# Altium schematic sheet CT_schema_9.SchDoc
size 254 x 194 mm
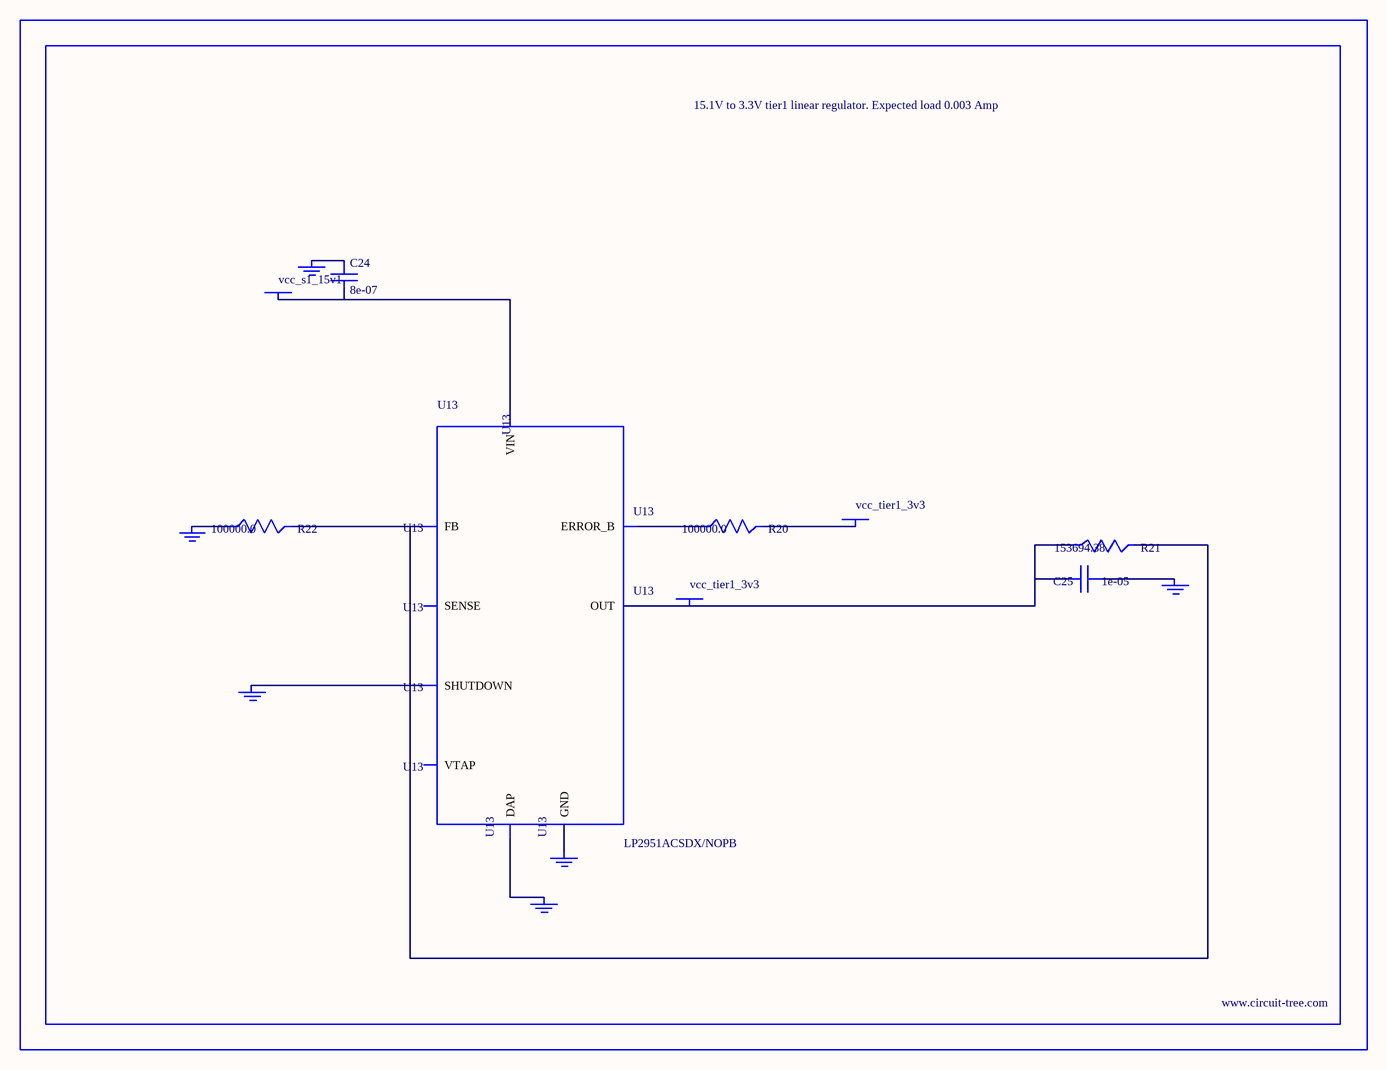
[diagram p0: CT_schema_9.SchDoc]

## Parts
BORDER8  (no value)
C24  8e-07  [R0603]
C25  1e-05  [C1210]
GND_INSTANCE_8_0  (no value)
GND_INSTANCE_8_1  (no value)
GND_INSTANCE_8_2  (no value)
GND_INSTANCE_8_3  (no value)
GND_INSTANCE_8_4  (no value)
GND_INSTANCE_8_5  (no value)
POWER_INSTANCE_8_0  vcc_tier1_3v3
POWER_INSTANCE_8_1  vcc_s1_15v1
POWER_INSTANCE_8_2  vcc_tier1_3v3
R20  100000.0  [R0603]
R21  153694.38  [R0603]
R22  100000.0  [R0603]
U13  LP2951ACSDX/NOPB  [WSON-8]

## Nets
NetC24_1: C24.1 GND_INSTANCE_8_3.0(GND)
NetC24_2: C24.2 POWER_INSTANCE_8_1.0(PWR) U13.8(VIN)
NetC25_1: C25.1 GND_INSTANCE_8_0.0(GND)
NetC25_2: C25.2 POWER_INSTANCE_8_2.0(PWR) R21.1 U13.1(OUT)
NetGND_INSTANCE_8_1_0: GND_INSTANCE_8_1.0(GND) U13.3(SHUTDOWN)
NetGND_INSTANCE_8_2_0: GND_INSTANCE_8_2.0(GND) R22.1
NetGND_INSTANCE_8_4_0: GND_INSTANCE_8_4.0(GND) U13.PAD(DAP)
NetGND_INSTANCE_8_5_0: GND_INSTANCE_8_5.0(GND) U13.4(GND)
NetPOWER_INSTANCE_8_0_0: POWER_INSTANCE_8_0.0(PWR) R20.2
NetR20_1: R20.1 U13.5(ERROR_B)
NetR21_2: R21.2 R22.2 U13.7(FB)

Not connected (* = marked no-connect by the designer): U13 2(SENSE) 6(VTAP)

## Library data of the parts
BORDER8 = BORDER_PAGE8
C24 = C24
C25 = GRM32DR61E106MA12L
GND_INSTANCE_8_0-GND_INSTANCE_8_5 = GND
POWER_INSTANCE_8_0-POWER_INSTANCE_8_2 = PWR
R20 R22 = RC0603JR-07100KL
R21 = R21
